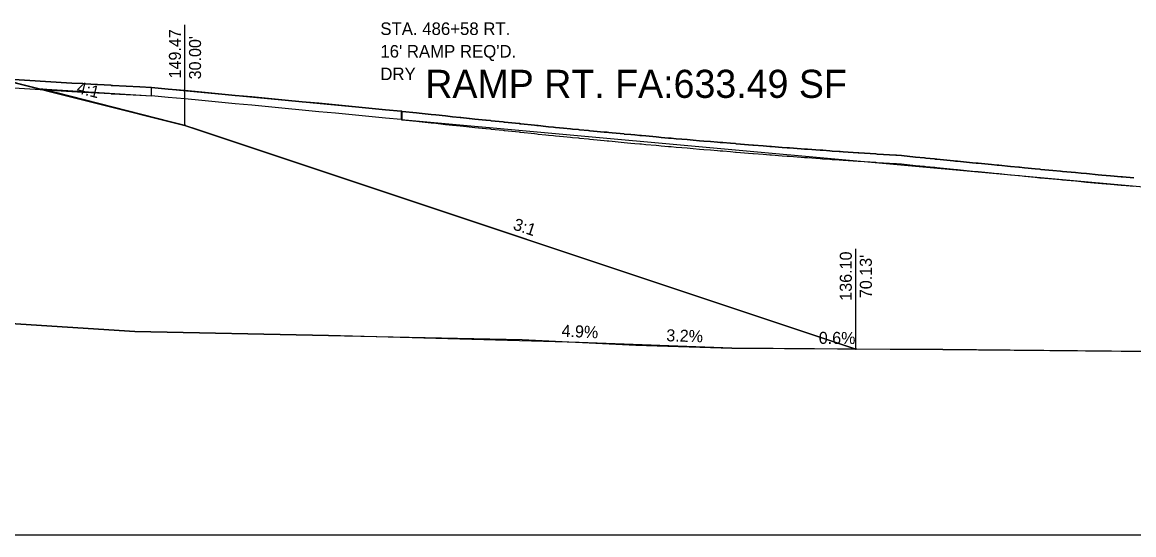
# Model space of a CAD drawing. Extents: x -26 to 4303, y -13 to 10775.
# Drawn here: x 3170.3 to 3236.8, y 5000 to 5030.6 of the extents above; entities that cross this region are included whole.
import ezdxf

# ---------------------------------------------------------------- set-up
doc = ezdxf.new("R2010")
doc.units = 0
for name, color, linetype in [('CONST_LV3', 7, 'Continuous'), ('CONST_PROF_LV1', 7, 'Continuous'), ('Default', 7, 'Continuous'), ('DTM_CONTOURS_MINOR', 7, 'Continuous'), ('DTM_P_FINISHED_GRADE', 7, 'Continuous'), ('DTM_X_GROUND', 7, 'Continuous'), ('X_PROFILES_1', 7, 'Continuous'), ('XS_CELL', 7, 'Continuous'), ('XS_P_DR_GRAVEL', 7, 'Continuous'), ('XS_P_DRAINAGE', 7, 'Continuous'), ('XS_P_GROUND', 7, 'Continuous'), ('XS_P_TX_CLEARZONE', 7, 'Continuous'), ('XS_P_TX_FS_BS', 7, 'Continuous'), ('XS_SHEET_EW_TX_AREA', 7, 'Continuous'), ('XS_SHEET_EW_TX_VOLUME', 7, 'Continuous')]:
    doc.layers.add(name, color=color, linetype=linetype)

msp = doc.modelspace()

# ---------------------------------------------------------------- linework, layer by layer
at = {"layer": 'CONST_LV3'}
msp.add_lwpolyline([(3173.72, 5026.045), (3180, 5024.475)], dxfattribs=at)
at = {"layer": 'DTM_P_FINISHED_GRADE'}
msp.add_lwpolyline([(3169.146, 5027.262), (3170.398, 5027.182), (3173.226, 5027.003), (3173.879, 5026.968), (3173.97, 5026.965), (3175.558, 5026.869), (3175.592, 5026.867), (3175.626, 5026.866), (3175.66, 5026.865), (3177.289, 5026.777), (3177.292, 5026.776), (3177.295, 5026.776), (3178, 5026.742), (3178, 5026.742), (3179, 5026.647), (3180, 5026.552), (3181, 5026.457), (3182, 5026.362), (3183, 5026.267), (3184, 5026.172), (3185, 5026.077), (3186, 5025.982), (3187, 5025.887), (3188, 5025.792), (3189, 5025.697), (3190, 5025.602), (3191, 5025.507), (3192, 5025.412), (3192.941, 5025.322), (3192.961, 5025.317), (3193, 5025.309), (3193, 5025.309), (3193.859, 5025.222), (3194, 5025.202), (3194.001, 5025.202), (3194.726, 5025.128), (3194.999, 5025.096), (3195.002, 5025.096), (3195.59, 5025.035), (3195.594, 5025.034), (3195.998, 5024.991), (3196.01, 5024.99), (3196.464, 5024.941), (3196.505, 5024.937), (3196.996, 5024.886), (3197.016, 5024.885), (3197.336, 5024.849), (3197.992, 5024.783), (3198.023, 5024.78), (3198.275, 5024.757), (3198.31, 5024.754), (3199.031, 5024.677), (3199.087, 5024.666), (3199.11, 5024.664), (3200.001, 5024.578), (3200.031, 5024.576), (3200.038, 5024.563), (3200.1, 5024.558), (3200.915, 5024.486), (3201.046, 5024.463), (3201.127, 5024.456), (3201.595, 5024.41), (3201.741, 5024.396), (3202.053, 5024.363), (3202.155, 5024.355), (3202.635, 5024.307), (3203.059, 5024.266), (3203.185, 5024.255), (3203.535, 5024.219), (3203.604, 5024.213), (3204.139, 5024.163), (3204.216, 5024.156), (3204.441, 5024.132), (3205.068, 5024.074), (3205.248, 5024.059), (3205.353, 5024.045), (3205.547, 5024.029), (3206.273, 5023.959), (3206.28, 5023.953), (3206.68, 5023.918), (3206.915, 5023.899), (3207.201, 5023.873), (3207.312, 5023.86), (3207.572, 5023.839), (3208.188, 5023.789), (3208.343, 5023.768), (3208.49, 5023.756), (3208.925, 5023.717), (3209.083, 5023.704), (3209.374, 5023.677), (3209.714, 5023.651), (3210.038, 5023.621), (3210.404, 5023.589), (3210.787, 5023.559), (3211.047, 5023.539), (3211.433, 5023.502), (3211.861, 5023.469), (3212.021, 5023.457), (3212.167, 5023.444), (3212.641, 5023.408), (3212.936, 5023.381), (3212.969, 5023.376), (3213.225, 5023.357), (3213.702, 5023.315), (3213.971, 5023.295), (3214.01, 5023.289), (3214.592, 5023.247), (3214.987, 5023.216), (3215.085, 5023.206), (3215.726, 5023.16), (3216.016, 5023.137), (3216.159, 5023.125), (3216.862, 5023.076), (3217.062, 5023.059), (3217.232, 5023.046), (3217.999, 5022.993), (3218.143, 5022.983), (3218.156, 5022.982), (3218.568, 5022.954), (3218.708, 5022.941), (3219.137, 5022.912), (3219.202, 5022.907), (3219.375, 5022.894), (3220.277, 5022.834), (3220.31, 5022.832), (3221.329, 5022.765), (3221.415, 5022.758), (3221.416, 5022.757), (3222.531, 5022.687), (3222.554, 5022.685), (3222.555, 5022.685), (3222.871, 5022.665), (3223.694, 5022.581), (3223.707, 5022.58), (3224.235, 5022.526), (3224.316, 5022.518), (3224.833, 5022.466), (3224.883, 5022.46), (3224.987, 5022.452), (3225.971, 5022.351), (3226.099, 5022.34), (3226.217, 5022.329), (3227.107, 5022.239), (3227.331, 5022.218), (3227.449, 5022.208), (3228.242, 5022.128), (3228.591, 5022.095), (3228.681, 5022.088), (3229.376, 5022.018), (3229.88, 5021.97), (3229.914, 5021.969), (3230.224, 5021.938), (3230.867, 5021.874), (3231.147, 5021.846), (3231.2, 5021.844), (3231.916, 5021.776), (3232.38, 5021.73), (3232.496, 5021.718), (3233.276, 5021.649), (3233.613, 5021.615), (3233.94, 5021.588), (3234.637, 5021.524), (3234.845, 5021.503), (3235.364, 5021.457), (3236.001, 5021.4), (3236.076, 5021.393), (3236.758, 5021.331)], dxfattribs=at)
at = {"layer": 'DTM_X_GROUND'}
msp.add_lwpolyline([(3121.043, 5028.008), (3124.888, 5027.357), (3125.792, 5027.191), (3133.123, 5022.647), (3142.048, 5017.046), (3149.924, 5014.592), (3150.011, 5014.564), (3156.484, 5013.493), (3157.461, 5013.398), (3177.004, 5012.157), (3200.167, 5011.663), (3206.976, 5011.327), (3212.719, 5011.146), (3225.338, 5011.067), (3261.632, 5010.739), (3284.436, 5011.007), (3300, 5011.444)], dxfattribs=at)
at = {"layer": 'XS_CELL'}
msp.add_line((3150, 5000), (3300, 5000), dxfattribs=at)
at = {"layer": 'XS_P_DR_GRAVEL'}
for points in [[(3169.146, 5026.762), (3170.398, 5026.682), (3173.226, 5026.503), (3173.879, 5026.468), (3173.97, 5026.465), (3175.558, 5026.369), (3175.592, 5026.367), (3175.626, 5026.366), (3175.66, 5026.365), (3177.289, 5026.277), (3177.292, 5026.276), (3177.295, 5026.276), (3178, 5026.242), (3178, 5026.742), (3177.295, 5026.776), (3177.292, 5026.776), (3177.289, 5026.777), (3175.66, 5026.865), (3175.626, 5026.866), (3175.592, 5026.867), (3175.558, 5026.869), (3173.97, 5026.965), (3173.879, 5026.968), (3173.226, 5027.003), (3170.398, 5027.182), (3169.146, 5027.262)], [(3178, 5026.242), (3178, 5026.242), (3178, 5026.242)], [(3192.976, 5024.814), (3192.961, 5024.817), (3192.961, 5024.817), (3192.941, 5024.822), (3192.941, 5024.822), (3192, 5024.912), (3192, 5024.912), (3191, 5025.007), (3191, 5025.007), (3190, 5025.102), (3190, 5025.102), (3189, 5025.197), (3189, 5025.197), (3188, 5025.292), (3188, 5025.292), (3187, 5025.387), (3187, 5025.387), (3186, 5025.482), (3186, 5025.482), (3185, 5025.577), (3185, 5025.577), (3184, 5025.672), (3184, 5025.672), (3183, 5025.767), (3183, 5025.767), (3182, 5025.862), (3182, 5025.862), (3181, 5025.957), (3181, 5025.957), (3180, 5026.052), (3180, 5026.052), (3180, 5026.052), (3179, 5026.147), (3179, 5026.147), (3178, 5026.242)], [(3192.976, 5025.314), (3192.976, 5024.814), (3193, 5024.809), (3193, 5024.809), (3193.859, 5024.722), (3194, 5024.702), (3194.001, 5024.702), (3194.726, 5024.628), (3194.999, 5024.596), (3195.002, 5024.596), (3195.59, 5024.535), (3195.594, 5024.534), (3195.998, 5024.491), (3196.01, 5024.49), (3196.464, 5024.441), (3196.505, 5024.437), (3196.996, 5024.386), (3197.016, 5024.385), (3197.336, 5024.349), (3197.992, 5024.283), (3198.023, 5024.28), (3198.275, 5024.257), (3198.31, 5024.254), (3199.031, 5024.177), (3199.087, 5024.166), (3199.11, 5024.164), (3200.001, 5024.078), (3200.031, 5024.076), (3200.038, 5024.063), (3200.1, 5024.058), (3200.915, 5023.986), (3201.046, 5023.963), (3201.127, 5023.956), (3201.595, 5023.91), (3201.741, 5023.896), (3202.053, 5023.863), (3202.155, 5023.855), (3202.635, 5023.807), (3203.059, 5023.766), (3203.185, 5023.755), (3203.535, 5023.719), (3203.604, 5023.713), (3204.139, 5023.663), (3204.216, 5023.656), (3204.441, 5023.632), (3205.068, 5023.574), (3205.248, 5023.559), (3205.353, 5023.545), (3205.547, 5023.529), (3206.273, 5023.459), (3206.28, 5023.453), (3206.68, 5023.418), (3206.915, 5023.399), (3207.201, 5023.373), (3207.312, 5023.36), (3207.572, 5023.339), (3208.188, 5023.289), (3208.343, 5023.268), (3208.49, 5023.256), (3208.925, 5023.217), (3209.083, 5023.204), (3209.374, 5023.177), (3209.714, 5023.151), (3210.038, 5023.121), (3210.404, 5023.089), (3210.787, 5023.059), (3211.047, 5023.039), (3211.433, 5023.002), (3211.861, 5022.969), (3212.021, 5022.957), (3212.167, 5022.944), (3212.641, 5022.908), (3212.936, 5022.881), (3212.969, 5022.876), (3213.225, 5022.857), (3213.702, 5022.815), (3213.971, 5022.795), (3214.01, 5022.789), (3214.592, 5022.747), (3214.987, 5022.716), (3215.085, 5022.706), (3215.726, 5022.66), (3216.016, 5022.637), (3216.159, 5022.625), (3216.862, 5022.576), (3217.062, 5022.559), (3217.232, 5022.546), (3217.999, 5022.493), (3218.143, 5022.483), (3218.156, 5022.482), (3218.568, 5022.454), (3218.708, 5022.441), (3219.137, 5022.412), (3219.202, 5022.407), (3219.375, 5022.394), (3220.277, 5022.334), (3220.31, 5022.332), (3221.329, 5022.265), (3221.415, 5022.258), (3221.416, 5022.257), (3222.531, 5022.187), (3222.554, 5022.185), (3222.555, 5022.185), (3222.871, 5022.165), (3223.694, 5022.081), (3223.707, 5022.08), (3224.235, 5022.026), (3224.316, 5022.018), (3224.833, 5021.966), (3224.883, 5021.96), (3224.987, 5021.952), (3225.971, 5021.851), (3226.099, 5021.84), (3226.217, 5021.829), (3227.107, 5021.739), (3227.331, 5021.718), (3227.449, 5021.708), (3228.242, 5021.628), (3228.591, 5021.595), (3228.681, 5021.588), (3229.376, 5021.518), (3229.88, 5021.47), (3229.914, 5021.469), (3230.224, 5021.438), (3230.867, 5021.374), (3231.147, 5021.346), (3231.2, 5021.344), (3231.916, 5021.276), (3232.38, 5021.23), (3232.496, 5021.218), (3233.276, 5021.149), (3233.613, 5021.115), (3233.94, 5021.088), (3234.637, 5021.024), (3234.845, 5021.003), (3235.364, 5020.957), (3236.001, 5020.9), (3236.076, 5020.893), (3236.758, 5020.831)], [(3236.758, 5021.331), (3236.076, 5021.393), (3236.001, 5021.4), (3235.364, 5021.457), (3234.845, 5021.503), (3234.637, 5021.524), (3233.94, 5021.588), (3233.613, 5021.615), (3233.276, 5021.649), (3232.496, 5021.718), (3232.38, 5021.73), (3231.916, 5021.776), (3231.2, 5021.844), (3231.147, 5021.846), (3230.867, 5021.874), (3230.224, 5021.938), (3229.914, 5021.969), (3229.88, 5021.97), (3229.376, 5022.018), (3228.681, 5022.088), (3228.591, 5022.095), (3228.242, 5022.128), (3227.449, 5022.208), (3227.331, 5022.218), (3227.107, 5022.239), (3226.217, 5022.329), (3226.099, 5022.34), (3225.971, 5022.351), (3224.987, 5022.452), (3224.883, 5022.46), (3224.833, 5022.466), (3224.316, 5022.518), (3224.235, 5022.526), (3223.707, 5022.58), (3223.694, 5022.581), (3222.871, 5022.665), (3222.555, 5022.685), (3222.554, 5022.685), (3222.531, 5022.687), (3221.416, 5022.757), (3221.415, 5022.758), (3221.329, 5022.765), (3220.31, 5022.832), (3220.277, 5022.834), (3219.375, 5022.894), (3219.202, 5022.907), (3219.137, 5022.912), (3218.708, 5022.941), (3218.568, 5022.954), (3218.156, 5022.982), (3218.143, 5022.983), (3217.999, 5022.993), (3217.232, 5023.046), (3217.062, 5023.059), (3216.862, 5023.076), (3216.159, 5023.125), (3216.016, 5023.137), (3215.726, 5023.16), (3215.085, 5023.206), (3214.987, 5023.216), (3214.592, 5023.247), (3214.01, 5023.289), (3213.971, 5023.295), (3213.702, 5023.315), (3213.225, 5023.357), (3212.969, 5023.376), (3212.936, 5023.381), (3212.641, 5023.408), (3212.167, 5023.444), (3212.021, 5023.457), (3211.861, 5023.469), (3211.433, 5023.502), (3211.047, 5023.539), (3210.787, 5023.559), (3210.404, 5023.589), (3210.038, 5023.621), (3209.714, 5023.651), (3209.374, 5023.677), (3209.083, 5023.704), (3208.925, 5023.717), (3208.49, 5023.756), (3208.343, 5023.768), (3208.188, 5023.789), (3207.572, 5023.839), (3207.312, 5023.86), (3207.201, 5023.873), (3206.915, 5023.899), (3206.68, 5023.918), (3206.28, 5023.953), (3206.273, 5023.959), (3205.547, 5024.029), (3205.353, 5024.045), (3205.248, 5024.059), (3205.068, 5024.074), (3204.441, 5024.132), (3204.216, 5024.156), (3204.139, 5024.163), (3203.604, 5024.213), (3203.535, 5024.219), (3203.185, 5024.255), (3203.059, 5024.266), (3202.635, 5024.307), (3202.155, 5024.355), (3202.053, 5024.363), (3201.741, 5024.396), (3201.595, 5024.41), (3201.127, 5024.456), (3201.046, 5024.463), (3200.915, 5024.486), (3200.1, 5024.558), (3200.038, 5024.563), (3200.031, 5024.576), (3200.001, 5024.578), (3199.11, 5024.664), (3199.087, 5024.666), (3199.031, 5024.677), (3198.31, 5024.754), (3198.275, 5024.757), (3198.023, 5024.78), (3197.992, 5024.783), (3197.336, 5024.849), (3197.016, 5024.885), (3196.996, 5024.886), (3196.505, 5024.937), (3196.464, 5024.941), (3196.01, 5024.99), (3195.998, 5024.991), (3195.594, 5025.034), (3195.59, 5025.035), (3195.002, 5025.096), (3194.999, 5025.096), (3194.726, 5025.128), (3194.001, 5025.202), (3194, 5025.202), (3193.859, 5025.222), (3193, 5025.309), (3193, 5025.309), (3192.976, 5025.314)]]:
    msp.add_lwpolyline(points, dxfattribs=at)
at = {"layer": 'XS_P_GROUND'}
for points in [[(3220.13, 5011.099), (3180.781, 5024.215), (3180, 5024.475), (3179.766, 5024.533), (3168, 5027.475)], [(3178, 5026.742), (3178, 5026.742), (3178, 5026.742)], [(3192.976, 5025.314), (3192.961, 5025.317), (3192.941, 5025.322), (3192.941, 5025.322), (3192, 5025.412), (3192, 5025.412), (3191, 5025.507), (3191, 5025.507), (3190, 5025.602), (3190, 5025.602), (3189, 5025.697), (3189, 5025.697), (3188, 5025.792), (3188, 5025.792), (3187, 5025.887), (3187, 5025.887), (3186, 5025.982), (3186, 5025.982), (3185, 5026.077), (3185, 5026.077), (3184, 5026.172), (3184, 5026.172), (3183, 5026.267), (3183, 5026.267), (3182, 5026.362), (3182, 5026.362), (3181, 5026.457), (3181, 5026.457), (3180, 5026.552), (3180, 5026.552), (3179, 5026.647), (3179, 5026.647), (3178, 5026.742)]]:
    msp.add_lwpolyline(points, dxfattribs=at)
at = {"layer": 'XS_P_TX_CLEARZONE'}
for p, q in [((3180, 5024.475), (3180, 5030.475)), ((3180, 5024.475), (3180, 5030.475)), ((3180, 5024.475), (3180, 5030.475)), ((3180, 5024.475), (3180, 5030.475)), ((3220.13, 5011.099), (3220.13, 5017.099)), ((3220.13, 5011.099), (3220.13, 5017.099)), ((3220.13, 5011.099), (3220.13, 5017.099)), ((3220.13, 5011.099), (3220.13, 5017.099)), ((3220.13, 5011.099), (3220.13, 5017.099))]:
    msp.add_line(p, q, dxfattribs=at)
at = {"layer": 'XS_SHEET_EW_TX_AREA'}
for points in [[(3220.13, 5011.099), (3212.719, 5011.146), (3203.572, 5011.495), (3188.585, 5011.91), (3177.004, 5012.157), (3157.461, 5013.398), (3149.924, 5014.592), (3142.048, 5017.046), (3127.413, 5026.186), (3127.141, 5026.354), (3130.47, 5027.122), (3136, 5027.343), (3136, 5026.906), (3134.007, 5026.872), (3134, 5026.212), (3150, 5026.519), (3166, 5026.199), (3165.986, 5026.878), (3164, 5026.911), (3164, 5027.343), (3168.925, 5027.244), (3180, 5024.475)], [(3271.851, 5010.859), (3261.632, 5010.739), (3243.485, 5010.903), (3225.338, 5011.067), (3220.13, 5011.099), (3180, 5024.475), (3171.412, 5026.649), (3178, 5026.242), (3178, 5026.742), (3192.941, 5025.322), (3192.941, 5024.822), (3239.318, 5020.614), (3255.413, 5015.905)]]:
    msp.add_lwpolyline(points, close=True, dxfattribs=at)

# ---------------------------------------------------------------- texts
at = {"layer": 'CONST_PROF_LV1'}
msp.add_text('X', height=0.12, dxfattribs=at).set_placement((3179.961, 5024.415))
at = {"layer": 'Default'}
msp.add_text('X', height=0.12, dxfattribs=at).set_placement((3179.961, 5024.415))
at = {"layer": 'DTM_CONTOURS_MINOR'}
msp.add_text('X', height=0.12, dxfattribs=at).set_placement((3220.091, 5011.039))
at = {"layer": 'X_PROFILES_1'}
msp.add_text('X', height=0.12, dxfattribs=at).set_placement((3220.091, 5011.039))
at = {"layer": 'XS_P_DRAINAGE'}
for s, p in [('STA. 486+58 RT.', (3191.686, 5029.877)), ("16' RAMP REQ'D.", (3191.686, 5028.527)), ('DRY', (3191.686, 5027.177))]:
    msp.add_text(s, height=0.75, dxfattribs=at).set_placement(p)
at = {"layer": 'XS_P_TX_CLEARZONE'}
for s, p in [('149.47', (3179.76, 5027.279)), ('149.47', (3179.76, 5027.279)), ('149.47', (3179.76, 5027.279)), ('149.47', (3179.76, 5027.279)), ("30.00'", (3180.96, 5027.222)), ("30.00'", (3180.96, 5027.222)), ("30.00'", (3180.96, 5027.222)), ("30.00'", (3180.96, 5027.222)), ('136.10', (3219.89, 5013.989)), ('136.10', (3219.89, 5013.989)), ('136.10', (3219.89, 5013.989)), ('136.10', (3219.89, 5013.989)), ('136.10', (3219.89, 5013.989)), ("70.13'", (3221.09, 5014.142)), ("70.13'", (3221.09, 5014.142)), ("70.13'", (3221.09, 5014.142)), ("70.13'", (3221.09, 5014.142)), ("70.13'", (3221.09, 5014.142))]:
    msp.add_text(s, height=0.72, rotation=90, dxfattribs=at).set_placement(p)
at = {"layer": 'XS_P_TX_FS_BS'}
for s, rotation, p in [('4:1', 345.96376, (3173.479, 5026.414)), ('3:1', 341.56677, (3199.579, 5018.265)), ('4.9%', 357.17811, (3202.514, 5011.848)), ('3.2%', 358.18701, (3208.784, 5011.57)), ('0.6%', 359.64256, (3217.912, 5011.413))]:
    msp.add_text(s, height=0.72, rotation=rotation, dxfattribs=at).set_placement(p)
at = {"layer": 'XS_SHEET_EW_TX_VOLUME'}
msp.add_text('RAMP RT. FA:633.49 SF', height=1.68, dxfattribs=at).set_placement((3194.375, 5026.117))

doc.saveas('drawing.dxf')
